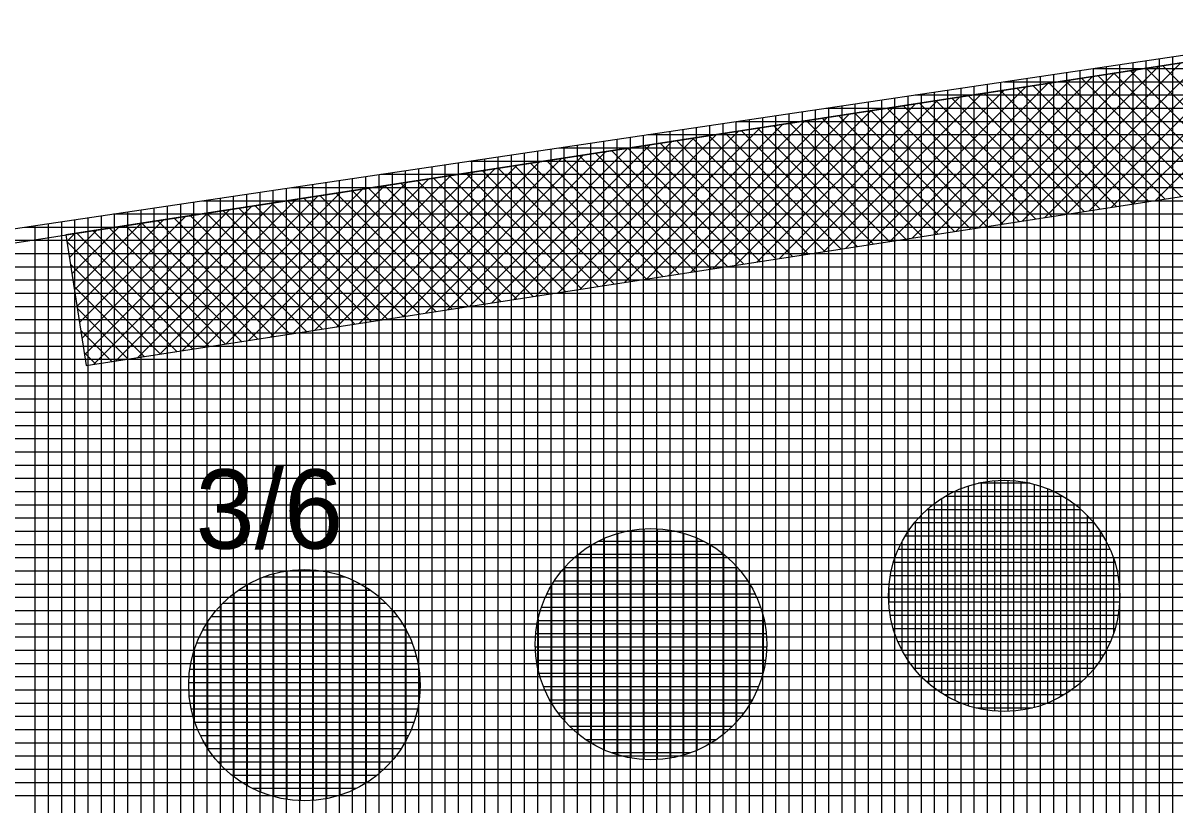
# Model space of a CAD drawing. Extents: x -565346 to -564154, y -1097386 to -1095620.
# Drawn here: x -564915.05 to -564897.63, y -1095802.12 to -1095790.29 of the extents above; entities that cross this region are included whole.
import ezdxf

# ---------------------------------------------------------------- set-up
doc = ezdxf.new("R2010")
doc.units = 0
for name, color, linetype in [('Vrstva 13', 7, 'Continuous'), ('Vrstva 40', 7, 'Continuous'), ('Vrstva 41', 7, 'Continuous'), ('Vrstva 42', 7, 'Continuous'), ('Vrstva 43', 7, 'Continuous'), ('Vrstva 44', 7, 'Continuous')]:
    doc.layers.add(name, color=color, linetype=linetype)

msp = doc.modelspace()

# ---------------------------------------------------------------- linework, layer by layer
at = {"layer": 'Vrstva 13'}
msp.add_line((-564961.71, -1095800.8), (-564879.81, -1095788.15), dxfattribs=at)
at = {"layer": 'Vrstva 41'}
for p, q in [((-564898.596, -1095793.076), (-564896.202, -1095790.682)), ((-564898.261, -1095793.024), (-564895.867, -1095790.63)), ((-564897.927, -1095792.972), (-564895.533, -1095790.578)), ((-564899.599, -1095793.231), (-564897.205, -1095790.837)), ((-564899.265, -1095793.179), (-564896.871, -1095790.785)), ((-564898.93, -1095793.127), (-564896.536, -1095790.733)), ((-564900.603, -1095793.386), (-564898.209, -1095790.992)), ((-564900.268, -1095793.334), (-564897.874, -1095790.94)), ((-564899.934, -1095793.282), (-564897.54, -1095790.888)), ((-564896.555, -1095792.761), (-564898.309, -1095791.007)), ((-564896.31, -1095792.723), (-564898.064, -1095790.969)), ((-564896.065, -1095792.685), (-564897.819, -1095790.932)), ((-564901.941, -1095793.592), (-564899.547, -1095791.198)), ((-564901.606, -1095793.541), (-564899.212, -1095791.147)), ((-564901.272, -1095793.489), (-564898.878, -1095791.095)), ((-564900.937, -1095793.437), (-564898.543, -1095791.043)), ((-564897.78, -1095792.95), (-564899.534, -1095791.196)), ((-564897.535, -1095792.912), (-564899.289, -1095791.159)), ((-564897.29, -1095792.874), (-564899.044, -1095791.121)), ((-564897.045, -1095792.836), (-564898.799, -1095791.083)), ((-564896.8, -1095792.798), (-564898.554, -1095791.045)), ((-564902.944, -1095793.747), (-564900.55, -1095791.354)), ((-564902.61, -1095793.696), (-564900.216, -1095791.302)), ((-564902.275, -1095793.644), (-564899.881, -1095791.25)), ((-564899.005, -1095793.139), (-564900.759, -1095791.386)), ((-564898.76, -1095793.101), (-564900.514, -1095791.348)), ((-564898.515, -1095793.063), (-564900.269, -1095791.31)), ((-564898.27, -1095793.025), (-564900.024, -1095791.272)), ((-564898.025, -1095792.988), (-564899.779, -1095791.234)), ((-564904.282, -1095793.954), (-564901.888, -1095791.56)), ((-564903.948, -1095793.902), (-564901.554, -1095791.509)), ((-564903.613, -1095793.851), (-564901.219, -1095791.457)), ((-564903.279, -1095793.799), (-564900.885, -1095791.405)), ((-564899.985, -1095793.29), (-564901.739, -1095791.537)), ((-564899.74, -1095793.252), (-564901.494, -1095791.499)), ((-564899.495, -1095793.215), (-564901.249, -1095791.461)), ((-564899.25, -1095793.177), (-564901.004, -1095791.423)), ((-564905.286, -1095794.109), (-564902.892, -1095791.715)), ((-564904.951, -1095794.057), (-564902.558, -1095791.664)), ((-564904.617, -1095794.006), (-564902.223, -1095791.612)), ((-564901.21, -1095793.48), (-564902.964, -1095791.726)), ((-564900.965, -1095793.442), (-564902.719, -1095791.688)), ((-564900.72, -1095793.404), (-564902.474, -1095791.651)), ((-564900.475, -1095793.366), (-564902.229, -1095791.613)), ((-564900.23, -1095793.328), (-564901.984, -1095791.575)), ((-564906.289, -1095794.264), (-564903.896, -1095791.87)), ((-564905.955, -1095794.212), (-564903.561, -1095791.819)), ((-564905.62, -1095794.161), (-564903.227, -1095791.767)), ((-564902.19, -1095793.631), (-564903.944, -1095791.878)), ((-564901.945, -1095793.593), (-564903.699, -1095791.84)), ((-564901.7, -1095793.555), (-564903.454, -1095791.802)), ((-564901.455, -1095793.517), (-564903.209, -1095791.764)), ((-564907.627, -1095794.471), (-564905.234, -1095792.077)), ((-564907.293, -1095794.419), (-564904.899, -1095792.025)), ((-564906.958, -1095794.367), (-564904.565, -1095791.974)), ((-564906.624, -1095794.316), (-564904.23, -1095791.922)), ((-564903.415, -1095793.82), (-564905.169, -1095792.067)), ((-564903.17, -1095793.782), (-564904.924, -1095792.029)), ((-564902.925, -1095793.744), (-564904.679, -1095791.991)), ((-564902.68, -1095793.707), (-564904.434, -1095791.953)), ((-564902.435, -1095793.669), (-564904.189, -1095791.915)), ((-564908.631, -1095794.626), (-564906.237, -1095792.232)), ((-564908.296, -1095794.574), (-564905.903, -1095792.18)), ((-564907.962, -1095794.522), (-564905.568, -1095792.129)), ((-564904.64, -1095794.009), (-564906.394, -1095792.256)), ((-564904.395, -1095793.971), (-564906.149, -1095792.218)), ((-564904.15, -1095793.934), (-564905.904, -1095792.18)), ((-564903.905, -1095793.896), (-564905.659, -1095792.142)), ((-564903.66, -1095793.858), (-564905.414, -1095792.105)), ((-564909.635, -1095794.781), (-564907.241, -1095792.387)), ((-564909.3, -1095794.729), (-564906.906, -1095792.335)), ((-564908.965, -1095794.677), (-564906.572, -1095792.284)), ((-564905.62, -1095794.161), (-564907.374, -1095792.407)), ((-564905.375, -1095794.123), (-564907.129, -1095792.37)), ((-564905.13, -1095794.085), (-564906.884, -1095792.332)), ((-564904.885, -1095794.047), (-564906.639, -1095792.294)), ((-564910.973, -1095794.987), (-564908.579, -1095792.594)), ((-564910.638, -1095794.936), (-564908.244, -1095792.542)), ((-564910.304, -1095794.884), (-564907.91, -1095792.49)), ((-564909.969, -1095794.832), (-564907.575, -1095792.439)), ((-564906.845, -1095794.35), (-564908.599, -1095792.597)), ((-564906.6, -1095794.312), (-564908.354, -1095792.559)), ((-564906.355, -1095794.274), (-564908.109, -1095792.521)), ((-564906.11, -1095794.236), (-564907.864, -1095792.483)), ((-564905.865, -1095794.199), (-564907.619, -1095792.445)), ((-564911.976, -1095795.142), (-564909.582, -1095792.749)), ((-564911.642, -1095795.091), (-564909.248, -1095792.697)), ((-564911.307, -1095795.039), (-564908.913, -1095792.645)), ((-564907.825, -1095794.501), (-564909.579, -1095792.748)), ((-564907.58, -1095794.463), (-564909.334, -1095792.71)), ((-564907.335, -1095794.426), (-564909.089, -1095792.672)), ((-564907.09, -1095794.388), (-564908.844, -1095792.634)), ((-564913.314, -1095795.349), (-564910.92, -1095792.955)), ((-564912.98, -1095795.297), (-564910.586, -1095792.904)), ((-564912.645, -1095795.246), (-564910.251, -1095792.852)), ((-564912.311, -1095795.194), (-564909.917, -1095792.8)), ((-564909.05, -1095794.69), (-564910.804, -1095792.937)), ((-564908.805, -1095794.653), (-564910.559, -1095792.899)), ((-564908.56, -1095794.615), (-564910.314, -1095792.861)), ((-564908.315, -1095794.577), (-564910.069, -1095792.824)), ((-564908.07, -1095794.539), (-564909.824, -1095792.786)), ((-564914.12, -1095795.306), (-564911.924, -1095793.11)), ((-564913.983, -1095795.452), (-564911.589, -1095793.059)), ((-564913.649, -1095795.401), (-564911.255, -1095793.007)), ((-564910.275, -1095794.88), (-564912.029, -1095793.126)), ((-564910.03, -1095794.842), (-564911.784, -1095793.089)), ((-564909.785, -1095794.804), (-564911.539, -1095793.051)), ((-564909.54, -1095794.766), (-564911.294, -1095793.013)), ((-564909.295, -1095794.728), (-564911.049, -1095792.975)), ((-564914.233, -1095794.571), (-564912.927, -1095793.265)), ((-564914.195, -1095794.816), (-564912.593, -1095793.214)), ((-564914.158, -1095795.061), (-564912.258, -1095793.162)), ((-564911.255, -1095795.031), (-564913.009, -1095793.278)), ((-564911.01, -1095794.993), (-564912.764, -1095793.24)), ((-564910.765, -1095794.955), (-564912.519, -1095793.202)), ((-564910.52, -1095794.918), (-564912.274, -1095793.164)), ((-564914.385, -1095793.591), (-564914.265, -1095793.472)), ((-564914.347, -1095793.836), (-564913.931, -1095793.42)), ((-564914.309, -1095794.081), (-564913.596, -1095793.369)), ((-564914.271, -1095794.326), (-564913.262, -1095793.317)), ((-564912.48, -1095795.22), (-564914.234, -1095793.467)), ((-564912.235, -1095795.182), (-564913.989, -1095793.429)), ((-564911.99, -1095795.145), (-564913.744, -1095793.391)), ((-564911.745, -1095795.107), (-564913.499, -1095793.353)), ((-564911.5, -1095795.069), (-564913.254, -1095793.316)), ((-564912.725, -1095795.258), (-564914.383, -1095793.6)), ((-564912.97, -1095795.296), (-564914.332, -1095793.935)), ((-564913.215, -1095795.334), (-564914.28, -1095794.269)), ((-564913.46, -1095795.372), (-564914.228, -1095794.604)), ((-564913.705, -1095795.409), (-564914.177, -1095794.938)), ((-564913.95, -1095795.447), (-564914.125, -1095795.273))]:
    msp.add_line(p, q, dxfattribs=at)
at = {"layer": 'Vrstva 42'}
msp.add_lwpolyline([(-564914.4, -1095793.493), (-564914.094, -1095795.47), (-564879.505, -1095790.127), (-564771.848, -1095770.879), (-564727.148, -1095761.474), (-564727.54, -1095759.52), (-564772.2, -1095768.91), (-564879.81, -1095788.15)], close=True, dxfattribs=at)
at = {"layer": 'Vrstva 43'}
for p, q in [((-564898.07, -1095790.862), (-564898.07, -1095806.022)), ((-564897.87, -1095790.832), (-564897.87, -1095805.992)), ((-564897.67, -1095790.802), (-564897.67, -1095805.963)), ((-564899.27, -1095791.04), (-564899.27, -1095806.2)), ((-564899.07, -1095791.01), (-564899.07, -1095806.171)), ((-564898.87, -1095790.98), (-564898.87, -1095806.141)), ((-564815.044, -1095790.98), (-564898.867, -1095790.98)), ((-564898.67, -1095790.951), (-564898.67, -1095806.111)), ((-564898.47, -1095790.921), (-564898.47, -1095806.082)), ((-564898.27, -1095790.891), (-564898.27, -1095806.052)), ((-564900.27, -1095791.188), (-564900.27, -1095806.349)), ((-564816.086, -1095791.18), (-564900.214, -1095791.18)), ((-564900.07, -1095791.159), (-564900.07, -1095806.319)), ((-564899.87, -1095791.129), (-564899.87, -1095806.29)), ((-564899.67, -1095791.099), (-564899.67, -1095806.26)), ((-564899.47, -1095791.07), (-564899.47, -1095806.23)), ((-564817.128, -1095791.38), (-564901.56, -1095791.38)), ((-564901.47, -1095791.367), (-564901.47, -1095806.527)), ((-564901.27, -1095791.337), (-564901.27, -1095806.497)), ((-564901.07, -1095791.307), (-564901.07, -1095806.468)), ((-564900.87, -1095791.277), (-564900.87, -1095806.438)), ((-564900.67, -1095791.248), (-564900.67, -1095806.408)), ((-564900.47, -1095791.218), (-564900.47, -1095806.379)), ((-564902.67, -1095791.545), (-564902.67, -1095806.705)), ((-564902.47, -1095791.515), (-564902.47, -1095806.676)), ((-564902.27, -1095791.485), (-564902.27, -1095806.646)), ((-564902.07, -1095791.456), (-564902.07, -1095806.616)), ((-564901.87, -1095791.426), (-564901.87, -1095806.587)), ((-564901.67, -1095791.396), (-564901.67, -1095806.557)), ((-564903.87, -1095791.723), (-564903.87, -1095806.884)), ((-564903.67, -1095791.693), (-564903.67, -1095806.854)), ((-564903.47, -1095791.664), (-564903.47, -1095806.824)), ((-564903.27, -1095791.634), (-564903.27, -1095806.794)), ((-564903.07, -1095791.604), (-564903.07, -1095806.765)), ((-564818.17, -1095791.58), (-564902.907, -1095791.58)), ((-564902.87, -1095791.574), (-564902.87, -1095806.735)), ((-564905.07, -1095791.901), (-564905.07, -1095807.062)), ((-564904.87, -1095791.871), (-564904.87, -1095807.032)), ((-564904.67, -1095791.842), (-564904.67, -1095807.002)), ((-564904.47, -1095791.812), (-564904.47, -1095806.973)), ((-564904.27, -1095791.782), (-564904.27, -1095806.943)), ((-564819.213, -1095791.78), (-564904.254, -1095791.78)), ((-564904.07, -1095791.753), (-564904.07, -1095806.913)), ((-564906.27, -1095792.079), (-564906.27, -1095807.24)), ((-564906.07, -1095792.05), (-564906.07, -1095807.21)), ((-564905.87, -1095792.02), (-564905.87, -1095807.181)), ((-564905.67, -1095791.99), (-564905.67, -1095807.151)), ((-564820.255, -1095791.98), (-564905.601, -1095791.98)), ((-564905.47, -1095791.961), (-564905.47, -1095807.121)), ((-564905.27, -1095791.931), (-564905.27, -1095807.092)), ((-564907.47, -1095792.258), (-564907.47, -1095807.418)), ((-564907.27, -1095792.228), (-564907.27, -1095807.389)), ((-564907.07, -1095792.198), (-564907.07, -1095807.359)), ((-564821.297, -1095792.18), (-564906.947, -1095792.18)), ((-564906.87, -1095792.168), (-564906.87, -1095807.329)), ((-564906.67, -1095792.139), (-564906.67, -1095807.299)), ((-564906.47, -1095792.109), (-564906.47, -1095807.27)), ((-564908.47, -1095792.406), (-564908.47, -1095807.567)), ((-564822.339, -1095792.38), (-564908.294, -1095792.38)), ((-564908.27, -1095792.376), (-564908.27, -1095807.537)), ((-564908.07, -1095792.347), (-564908.07, -1095807.507)), ((-564907.87, -1095792.317), (-564907.87, -1095807.478)), ((-564907.67, -1095792.287), (-564907.67, -1095807.448)), ((-564909.67, -1095792.584), (-564909.67, -1095807.745)), ((-564823.381, -1095792.58), (-564909.641, -1095792.58)), ((-564909.47, -1095792.555), (-564909.47, -1095807.715)), ((-564909.27, -1095792.525), (-564909.27, -1095807.686)), ((-564909.07, -1095792.495), (-564909.07, -1095807.656)), ((-564908.87, -1095792.465), (-564908.87, -1095807.626)), ((-564908.67, -1095792.436), (-564908.67, -1095807.597)), ((-564824.423, -1095792.78), (-564910.988, -1095792.78)), ((-564910.87, -1095792.763), (-564910.87, -1095807.923)), ((-564910.67, -1095792.733), (-564910.67, -1095807.894)), ((-564910.47, -1095792.703), (-564910.47, -1095807.864)), ((-564910.27, -1095792.673), (-564910.27, -1095807.834)), ((-564910.07, -1095792.644), (-564910.07, -1095807.804)), ((-564909.87, -1095792.614), (-564909.87, -1095807.775)), ((-564912.07, -1095792.941), (-564912.07, -1095808.102)), ((-564911.87, -1095792.911), (-564911.87, -1095808.072)), ((-564911.67, -1095792.881), (-564911.67, -1095808.042)), ((-564911.47, -1095792.852), (-564911.47, -1095808.012)), ((-564911.27, -1095792.822), (-564911.27, -1095807.983)), ((-564911.07, -1095792.792), (-564911.07, -1095807.953)), ((-564913.27, -1095793.119), (-564913.27, -1095808.28)), ((-564913.07, -1095793.089), (-564913.07, -1095808.25)), ((-564912.87, -1095793.06), (-564912.87, -1095808.22)), ((-564912.67, -1095793.03), (-564912.67, -1095808.191)), ((-564912.47, -1095793), (-564912.47, -1095808.161)), ((-564825.465, -1095792.98), (-564912.335, -1095792.98)), ((-564912.27, -1095792.97), (-564912.27, -1095808.131)), ((-564914.47, -1095793.297), (-564914.47, -1095808.458)), ((-564914.27, -1095793.267), (-564914.27, -1095808.428)), ((-564914.07, -1095793.238), (-564914.07, -1095808.399)), ((-564913.87, -1095793.208), (-564913.87, -1095808.369)), ((-564826.507, -1095793.18), (-564913.681, -1095793.18)), ((-564913.67, -1095793.178), (-564913.67, -1095808.339)), ((-564913.47, -1095793.149), (-564913.47, -1095808.309)), ((-564827.55, -1095793.38), (-564915.028, -1095793.38)), ((-564914.87, -1095793.357), (-564914.87, -1095808.517)), ((-564914.67, -1095793.327), (-564914.67, -1095808.488)), ((-564828.592, -1095793.58), (-564916.375, -1095793.58)), ((-564829.634, -1095793.78), (-564917.722, -1095793.78)), ((-564830.676, -1095793.98), (-564919.068, -1095793.98)), ((-564831.718, -1095794.18), (-564920.415, -1095794.18)), ((-564832.76, -1095794.38), (-564921.762, -1095794.38)), ((-564833.802, -1095794.58), (-564923.109, -1095794.58)), ((-564834.845, -1095794.78), (-564924.456, -1095794.78)), ((-564835.887, -1095794.98), (-564925.802, -1095794.98)), ((-564836.929, -1095795.18), (-564927.149, -1095795.18)), ((-564837.971, -1095795.38), (-564928.496, -1095795.38)), ((-564839.013, -1095795.58), (-564929.843, -1095795.58)), ((-564840.055, -1095795.78), (-564931.189, -1095795.78)), ((-564841.097, -1095795.98), (-564932.536, -1095795.98)), ((-564842.14, -1095796.18), (-564933.883, -1095796.18)), ((-564843.182, -1095796.38), (-564935.23, -1095796.38)), ((-564844.224, -1095796.58), (-564936.577, -1095796.58)), ((-564845.266, -1095796.78), (-564937.923, -1095796.78)), ((-564846.308, -1095796.98), (-564939.27, -1095796.98)), ((-564847.35, -1095797.18), (-564940.617, -1095797.18)), ((-564848.392, -1095797.38), (-564941.964, -1095797.38)), ((-564849.434, -1095797.58), (-564943.31, -1095797.58)), ((-564850.477, -1095797.78), (-564944.657, -1095797.78)), ((-564851.519, -1095797.98), (-564946.004, -1095797.98)), ((-564852.561, -1095798.18), (-564947.351, -1095798.18)), ((-564853.603, -1095798.38), (-564948.697, -1095798.38)), ((-564854.645, -1095798.58), (-564950.044, -1095798.58)), ((-564855.687, -1095798.78), (-564951.391, -1095798.78)), ((-564856.729, -1095798.98), (-564952.738, -1095798.98)), ((-564857.772, -1095799.18), (-564954.085, -1095799.18)), ((-564858.814, -1095799.38), (-564955.431, -1095799.38)), ((-564859.856, -1095799.58), (-564956.778, -1095799.58)), ((-564860.898, -1095799.78), (-564958.125, -1095799.78)), ((-564861.94, -1095799.98), (-564959.472, -1095799.98)), ((-564862.982, -1095800.18), (-564960.818, -1095800.18)), ((-564864.024, -1095800.38), (-564962.165, -1095800.38)), ((-564865.066, -1095800.58), (-564963.512, -1095800.58)), ((-564866.109, -1095800.78), (-564964.859, -1095800.78)), ((-564867.151, -1095800.98), (-564966.206, -1095800.98)), ((-564868.193, -1095801.18), (-564967.552, -1095801.18)), ((-564869.235, -1095801.38), (-564968.899, -1095801.38)), ((-564870.277, -1095801.58), (-564970.246, -1095801.58)), ((-564871.319, -1095801.78), (-564971.593, -1095801.78)), ((-564872.361, -1095801.98), (-564972.939, -1095801.98))]:
    msp.add_line(p, q, dxfattribs=at)
msp.add_lwpolyline([(-564584.17, -1095730.99), (-564361.01, -1095672.63), (-564329.81, -1095662.26), (-564326.21, -1095642.73), (-564394.52, -1095662.95), (-564454.33, -1095677.56), (-564516.6, -1095690.89), (-564574.04, -1095705.03), (-564590.74, -1095715.12), (-564631.48, -1095731.18), (-564693.31, -1095752.31), (-564772.2, -1095768.91), (-564879.81, -1095788.15), (-565039.47, -1095811.86), (-565040.85, -1095849.94), (-565025.81, -1095848.33), (-565025.24, -1095824.91), (-564877.52, -1095802.97), (-564694, -1095767.75), (-564603.8, -1095739.23), (-564594.74, -1095734.52)], close=True, dxfattribs=at)
at = {"layer": 'Vrstva 44'}
for p, q in [((-564900.76, -1095797.293), (-564900.76, -1095800.615)), ((-564899.822, -1095797.25), (-564900.604, -1095797.25)), ((-564900.56, -1095797.24), (-564900.56, -1095800.668)), ((-564900.36, -1095797.21), (-564900.36, -1095800.696)), ((-564900.16, -1095797.206), (-564900.16, -1095800.701)), ((-564899.96, -1095797.224), (-564899.96, -1095800.684)), ((-564899.76, -1095797.266), (-564899.76, -1095800.644)), ((-564901.16, -1095797.483), (-564901.16, -1095800.426)), ((-564899.323, -1095797.45), (-564901.106, -1095797.45)), ((-564900.96, -1095797.373), (-564900.96, -1095800.535)), ((-564899.56, -1095797.332), (-564899.56, -1095800.575)), ((-564899.36, -1095797.428), (-564899.36, -1095800.479)), ((-564899.05, -1095797.65), (-564901.379, -1095797.65)), ((-564901.36, -1095797.634), (-564901.36, -1095800.274)), ((-564899.16, -1095797.56), (-564899.16, -1095800.35)), ((-564898.96, -1095797.735), (-564898.96, -1095800.172)), ((-564905.86, -1095797.961), (-564905.86, -1095801.405)), ((-564905.66, -1095797.939), (-564905.66, -1095801.429)), ((-564905.46, -1095797.938), (-564905.46, -1095801.43)), ((-564905.26, -1095797.961), (-564905.26, -1095801.409)), ((-564905.06, -1095798.006), (-564905.06, -1095801.361)), ((-564898.858, -1095797.85), (-564901.569, -1095797.85)), ((-564901.56, -1095797.838), (-564901.56, -1095800.071)), ((-564898.76, -1095797.982), (-564898.76, -1095799.924)), ((-564904.752, -1095798.13), (-564906.357, -1095798.13)), ((-564906.26, -1095798.085), (-564906.26, -1095801.283)), ((-564906.06, -1095798.01), (-564906.06, -1095801.359)), ((-564904.86, -1095798.079), (-564904.86, -1095801.288)), ((-564904.66, -1095798.182), (-564904.66, -1095801.188)), ((-564901.76, -1095798.138), (-564901.76, -1095799.77)), ((-564898.718, -1095798.05), (-564901.712, -1095798.05)), ((-564904.446, -1095798.33), (-564906.66, -1095798.33)), ((-564906.66, -1095798.33), (-564906.66, -1095801.039)), ((-564906.46, -1095798.188), (-564906.46, -1095801.179)), ((-564904.46, -1095798.319), (-564904.46, -1095801.047)), ((-564898.612, -1095798.25), (-564901.815, -1095798.25)), ((-564904.241, -1095798.53), (-564906.869, -1095798.53)), ((-564906.86, -1095798.519), (-564906.86, -1095800.847)), ((-564904.26, -1095798.509), (-564904.26, -1095800.862)), ((-564898.54, -1095798.45), (-564901.888, -1095798.45)), ((-564898.56, -1095798.386), (-564898.56, -1095799.52)), ((-564911.46, -1095798.687), (-564911.46, -1095801.922)), ((-564910.173, -1095798.67), (-564911.42, -1095798.67)), ((-564911.26, -1095798.617), (-564911.26, -1095801.99)), ((-564911.06, -1095798.576), (-564911.06, -1095802.032)), ((-564910.86, -1095798.557), (-564910.86, -1095802.052)), ((-564910.66, -1095798.561), (-564910.66, -1095802.048)), ((-564910.46, -1095798.587), (-564910.46, -1095802.02)), ((-564910.26, -1095798.638), (-564910.26, -1095801.968)), ((-564898.493, -1095798.65), (-564901.936, -1095798.65)), ((-564909.794, -1095798.87), (-564911.794, -1095798.87)), ((-564911.66, -1095798.785), (-564911.66, -1095801.823)), ((-564910.06, -1095798.718), (-564910.06, -1095801.891)), ((-564909.86, -1095798.826), (-564909.86, -1095801.782)), ((-564907.06, -1095798.793), (-564907.06, -1095800.574)), ((-564904.089, -1095798.73), (-564907.019, -1095798.73)), ((-564904.06, -1095798.777), (-564904.06, -1095800.595)), ((-564898.469, -1095798.85), (-564901.961, -1095798.85)), ((-564901.96, -1095798.843), (-564901.96, -1095799.056)), ((-564911.86, -1095798.916), (-564911.86, -1095801.691)), ((-564909.66, -1095798.973), (-564909.66, -1095801.634)), ((-564903.977, -1095798.93), (-564907.133, -1095798.93)), ((-564898.468, -1095799.05), (-564901.961, -1095799.05)), ((-564912.06, -1095799.098), (-564912.06, -1095801.51)), ((-564909.554, -1095799.07), (-564912.032, -1095799.07)), ((-564909.46, -1095799.172), (-564909.46, -1095801.434)), ((-564903.895, -1095799.13), (-564907.213, -1095799.13)), ((-564912.26, -1095799.352), (-564912.26, -1095801.256)), ((-564909.385, -1095799.27), (-564912.206, -1095799.27)), ((-564903.841, -1095799.33), (-564907.266, -1095799.33)), ((-564907.26, -1095799.3), (-564907.26, -1095800.072)), ((-564903.86, -1095799.253), (-564903.86, -1095800.12)), ((-564898.49, -1095799.25), (-564901.937, -1095799.25)), ((-564909.256, -1095799.47), (-564912.331, -1095799.47)), ((-564909.26, -1095799.463), (-564909.26, -1095801.142)), ((-564903.813, -1095799.53), (-564907.296, -1095799.53)), ((-564898.538, -1095799.45), (-564901.89, -1095799.45)), ((-564909.165, -1095799.67), (-564912.423, -1095799.67)), ((-564903.807, -1095799.73), (-564907.303, -1095799.73)), ((-564898.611, -1095799.65), (-564901.819, -1095799.65)), ((-564909.101, -1095799.87), (-564912.489, -1095799.87)), ((-564912.46, -1095799.774), (-564912.46, -1095800.836)), ((-564898.712, -1095799.85), (-564901.716, -1095799.85)), ((-564909.061, -1095800.07), (-564912.527, -1095800.07)), ((-564909.06, -1095800.075), (-564909.06, -1095800.524)), ((-564903.823, -1095799.93), (-564907.286, -1095799.93)), ((-564898.852, -1095800.05), (-564901.576, -1095800.05)), ((-564909.045, -1095800.27), (-564912.542, -1095800.27)), ((-564903.862, -1095800.13), (-564907.245, -1095800.13)), ((-564899.038, -1095800.25), (-564901.388, -1095800.25)), ((-564903.929, -1095800.33), (-564907.178, -1095800.33)), ((-564909.054, -1095800.47), (-564912.534, -1095800.47)), ((-564904.025, -1095800.53), (-564907.085, -1095800.53)), ((-564899.306, -1095800.45), (-564901.119, -1095800.45)), ((-564909.085, -1095800.67), (-564912.504, -1095800.67)), ((-564904.151, -1095800.73), (-564906.955, -1095800.73)), ((-564899.786, -1095800.65), (-564900.642, -1095800.65)), ((-564909.14, -1095800.87), (-564912.45, -1095800.87)), ((-564904.328, -1095800.93), (-564906.782, -1095800.93)), ((-564909.221, -1095801.07), (-564912.366, -1095801.07)), ((-564904.572, -1095801.13), (-564906.537, -1095801.13)), ((-564909.337, -1095801.27), (-564912.251, -1095801.27)), ((-564909.49, -1095801.47), (-564912.097, -1095801.47)), ((-564904.962, -1095801.33), (-564906.143, -1095801.33)), ((-564909.703, -1095801.67), (-564911.887, -1095801.67)), ((-564910.015, -1095801.87), (-564911.573, -1095801.87))]:
    msp.add_line(p, q, dxfattribs=at)
for centre in [(-564900.214, -1095798.954), (-564905.554, -1095799.684), (-564910.794, -1095800.304)]:
    msp.add_circle(centre, 1.75, dxfattribs=at)

# ---------------------------------------------------------------- texts
at = {"layer": 'Vrstva 40'}
msp.add_text('3/6', height=1.2, dxfattribs=at).set_placement((-564912.44, -1095798.24))

doc.saveas('drawing.dxf')
